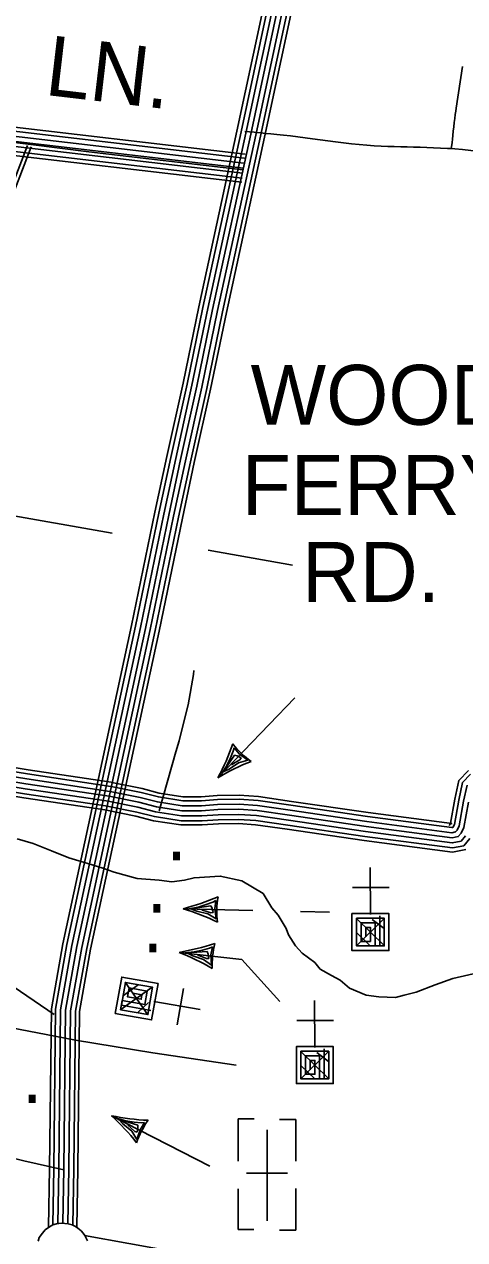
# Model space of a CAD drawing. Extents: x 1788175 to 1969470, y 584502 to 738744.
# Drawn here: x 1837495 to 1840217, y 713422 to 720928 of the extents above; entities that cross this region are included whole.
import ezdxf

# ---------------------------------------------------------------- set-up
doc = ezdxf.new("R2010")
doc.units = 0
for name, color, linetype in [('DESIGN - ROW - Right-of-Way and Easement Labels', 7, 'Continuous'), ('DESIGN - TRANSPORTATION - Text', 7, 'Continuous'), ('DESIGN - UTILITIES - Cable (Overhead) with Text', 7, 'Continuous'), ('DESIGN - UTILITIES - Cable (Underground) with Text', 7, 'Continuous'), ('SURVEY - CENTERLINE - Preliminary Text', 7, 'Continuous'), ('SURVEY - CONTOURS - Index with Text', 7, 'Continuous'), ('SURVEY - TRANSPORTATION - Roads', 7, 'Continuous'), ('SURVEY - VEGETATION - Features with Text', 7, 'Continuous')]:
    doc.layers.add(name, color=color, linetype=linetype)

msp = doc.modelspace()

# ---------------------------------------------------------------- linework, layer by layer
at = {"layer": 'DESIGN - ROW - Right-of-Way and Easement Labels'}
for p, q in [((1837232.7, 717927.5), (1838038.6, 717785.4)), ((1838630.4, 717681), (1839152.6, 717588.9))]:
    msp.add_line(p, q, dxfattribs=at)
at = {"layer": 'DESIGN - TRANSPORTATION - Text'}
msp.add_lwpolyline([(1837451.3, 715898), (1837549.3, 715868.6), (1837662.1, 715824.4), (1837770, 715780.3), (1837887.6, 715746), (1837980.8, 715716.6), (1838049.4, 715692), (1838191.6, 715652.8), (1838328.9, 715643), (1838407.4, 715633.2), (1838485.8, 715643), (1838544.7, 715657.7), (1838706.5, 715667.5), (1838838.8, 715638.1), (1838971.2, 715559.7), (1839025.2, 715471.4), (1839064.4, 715427.3), (1839113.4, 715343.9), (1839128.1, 715304.7), (1839172.2, 715236.1), (1839211.5, 715191.9), (1839289.9, 715133.1), (1839324.2, 715093.9), (1839392.9, 715054.6), (1839446.8, 715025.2), (1839505.7, 714976.2), (1839608.6, 714932.1), (1839687.1, 714922.3), (1839790, 714917.4), (1839844, 714932.1), (1839917.5, 714951.7), (1840035.2, 714995.8), (1840143.1, 715035), (1840314.7, 715074.3)], dxfattribs=at)
at = {"layer": 'DESIGN - UTILITIES - Cable (Overhead) with Text'}
for p, q in [((1838691.7, 716275.5), (1839166.5, 716768.3)), ((1838724.3, 716310.7), (1838795, 716414.6)), ((1838746.8, 716350.8), (1838769.8, 716397.7)), ((1838769.8, 716397.7), (1838786.3, 716439.2)), ((1838786.3, 716439.2), (1838791.1, 716459.5)), ((1838791.1, 716459.5), (1838825.6, 716420.4)), ((1838795, 716414.6), (1838811.5, 716410.5)), ((1838811.5, 716410.5), (1838835.7, 716397.4)), ((1838825.6, 716420.4), (1838877.1, 716383.9)), ((1838835.7, 716397.4), (1838827, 716385.2)), ((1838716.2, 716300.8), (1838746.8, 716350.8)), ((1838760.6, 716328.5), (1838724.3, 716310.7)), ((1838819.1, 716367.9), (1838760.6, 716328.5)), ((1838798, 716369), (1838776.6, 716355.8)), ((1838827, 716385.2), (1838798, 716369)), ((1838877.1, 716383.9), (1838819.1, 716367.9)), ((1838568.6, 715476.8), (1838618.8, 715491.5)), ((1838618.8, 715491.5), (1838660.5, 715507.4)), ((1838660.5, 715507.4), (1838678.8, 715517.6)), ((1838678.8, 715517.6), (1838673.2, 715465.8)), ((1838476, 715466.5), (1838907.6, 715455.9)), ((1838511.2, 715465.5), (1838568.6, 715476.8)), ((1838523.9, 715466.3), (1838648.3, 715484.5)), ((1838561.6, 715451.6), (1838523.9, 715466.3)), ((1838630.1, 715435.1), (1838561.6, 715451.6)), ((1838616.7, 715451.3), (1838592.5, 715458.2)), ((1838648.3, 715441), (1838616.7, 715451.3)), ((1838681.2, 715403.1), (1838630.1, 715435.1)), ((1838648.3, 715484.5), (1838656.4, 715469.5)), ((1838663.1, 715442.8), (1838648.3, 715441)), ((1838656.4, 715469.5), (1838663.1, 715442.8)), ((1838673.2, 715465.8), (1838681.2, 715403.1)), ((1839201.8, 715448.7), (1839382.2, 715444.3)), ((1838486.5, 715193.1), (1838544.7, 715199.8)), ((1838499.2, 715192.8), (1838624.7, 715201.1)), ((1838535.7, 715175.2), (1838499.2, 715192.8)), ((1838544.7, 715199.8), (1838595.8, 715210.5)), ((1838595.8, 715210.5), (1838638.7, 715223)), ((1838624.7, 715201.1), (1838631.6, 715185.5)), ((1838638.7, 715223), (1838657.7, 715231.7)), ((1838657.7, 715231.7), (1838648, 715180.5)), ((1838602.6, 715153.3), (1838535.7, 715175.2)), ((1838590.6, 715170.6), (1838567, 715179.4)), ((1838621.2, 715157.8), (1838590.6, 715170.6)), ((1838651.1, 715117.4), (1838602.6, 715153.3)), ((1838636.2, 715158.3), (1838621.2, 715157.8)), ((1838631.6, 715185.5), (1838636.2, 715158.3)), ((1838648, 715180.5), (1838651.1, 715117.4)), ((1838033.7, 714187.8), (1838642.6, 713875.6)), ((1838065, 714171.7), (1838121.6, 714156.9)), ((1838104.4, 714137.2), (1838076.7, 714166.8)), ((1838076.7, 714166.8), (1838196.7, 714129.1)), ((1838121.6, 714156.9), (1838173.2, 714148.3)), ((1838173.2, 714148.3), (1838217.7, 714144.5)), ((1838238.5, 714145.8), (1838211, 714101.5)), ((1838217.7, 714144.5), (1838238.5, 714145.8)), ((1838158.9, 714092.6), (1838104.4, 714137.2)), ((1838153.9, 714113), (1838135.1, 714129.7)), ((1838177.8, 714090), (1838153.9, 714113)), ((1838191, 714041.6), (1838158.9, 714092.6)), ((1838192, 714085.2), (1838177.8, 714090)), ((1838211, 714101.5), (1838191, 714041.6)), ((1838197.5, 714112.1), (1838192, 714085.2)), ((1838196.7, 714129.1), (1838197.5, 714112.1))]:
    msp.add_line(p, q, dxfattribs=at)
msp.add_lwpolyline([(1838451.5, 715196.8), (1838838.8, 715152.7), (1839074.2, 714892.8)], dxfattribs=at)
for centre, radius, start, end in [((1837323, 717007.6), 1552.3, 331.85818, 340.28596), ((1839205.8, 716809.1), 532.3, 217.64141, 234.49981), ((1839401.4, 715084.5), 1386.4, 111.34988, 120.78842), ((1838090.4, 716970.1), 1552.3, 284.38394, 292.81172), ((1839216.7, 715448.3), 532.3, 170.16717, 187.02557), ((1838078, 714138.5), 1386.4, 63.87564, 73.31418), ((1838186.2, 716726.2), 1552.3, 279.84039, 288.26817), ((1837949.5, 713904.5), 1386.4, 59.33209, 68.77062), ((1839188.4, 715120), 532.3, 165.62362, 182.48201), ((1838339.5, 715709.6), 1552.3, 258.63986, 267.06763), ((1837098.4, 713164.5), 1386.4, 38.13155, 47.57009), ((1838693, 713849.7), 532.3, 144.42308, 161.28148)]:
    msp.add_arc(centre, radius, start, end, dxfattribs=at)
at = {"layer": 'DESIGN - UTILITIES - Cable (Underground) with Text'}
for p, q in [((1839750.6, 715596.6), (1839522.6, 715596.6)), ((1838439.6, 714749.6), (1838479.3, 714974.2)), ((1839406.8, 714775.2), (1839178.7, 714775.2)), ((1838816.2, 714168.4), (1838816.2, 713907.6)), ((1838915.9, 714168.4), (1838816.8, 714168.4)), ((1839172.6, 714164.5), (1839072.8, 714164.5)), ((1839172.5, 713907.7), (1839172.5, 714164.5)), ((1839122.5, 713833.3), (1838868.8, 713833.3)), ((1838816.2, 713736.6), (1838816.2, 713485.2)), ((1839172.5, 713481.2), (1839172.5, 713739.3)), ((1838816.3, 713485.2), (1838914.6, 713485.2)), ((1839172.3, 713481.2), (1839072.8, 713481.2))]:
    msp.add_line(p, q, dxfattribs=at)
for points in [[(1839632.2, 715720.4), (1839634.6, 715430)], [(1839634.5, 715440.9), (1839634.6, 715435.8), (1839748.6, 715435.8), (1839748.6, 715207.7), (1839520.5, 715207.7), (1839520.5, 715435.8), (1839691.6, 715435.8), (1839691.6, 715431.8)], [(1839691.6, 715421.6), (1839691.6, 715236.2), (1839549, 715236.2), (1839549, 715407.3), (1839720.1, 715407.3), (1839720.1, 715236.2), (1839663.1, 715236.2), (1839663.1, 715378.8), (1839577.6, 715378.8), (1839577.6, 715264.8), (1839634.6, 715264.8), (1839634.6, 715350.3), (1839606.1, 715350.3), (1839606.1, 715293.3)], [(1839721.9, 715407.4), (1839546.9, 715235.3)], [(1839549.8, 715404.5), (1839719, 715238.3)], [(1839646.1, 715398.7), (1839719, 715343.2)], [(1839549.8, 715317), (1839631.5, 715238.3)], [(1838306.5, 714891.1), (1838301.5, 714891.9), (1838281.6, 714779.6), (1838057, 714819.3), (1838096.7, 715043.9), (1838321.3, 715004.2), (1838291.5, 714835.8), (1838287.6, 714836.5)], [(1838277.6, 714838.2), (1838095, 714870.5), (1838119.9, 715010.9), (1838288.3, 714981.1), (1838258.5, 714812.6), (1838090.1, 714842.4), (1838100, 714898.6), (1838240.4, 714873.7), (1838255.3, 714958), (1838143, 714977.8), (1838133, 714921.7), (1838217.3, 714906.8), (1838222.2, 714934.9), (1838166.1, 714944.8)], [(1838285.4, 714980.8), (1838092.3, 714843.2)], [(1838199.2, 714996), (1838107.5, 714929.3)], [(1838258.3, 714810.9), (1838119.3, 715013.1)], [(1838582.2, 714844.7), (1838295.7, 714892.9)], [(1839288.3, 714899.1), (1839290.8, 714608.6)], [(1838262.9, 714887.1), (1838195.6, 714824.9)], [(1839290.7, 714619.5), (1839290.8, 714614.5), (1839404.8, 714614.5), (1839404.8, 714386.4), (1839176.7, 714386.4), (1839176.7, 714614.5), (1839347.8, 714614.5), (1839347.8, 714610.4)], [(1839347.8, 714600.2), (1839347.8, 714414.9), (1839205.2, 714414.9), (1839205.2, 714585.9), (1839376.3, 714585.9), (1839376.3, 714414.9), (1839319.3, 714414.9), (1839319.3, 714557.4), (1839233.7, 714557.4), (1839233.7, 714443.4), (1839290.8, 714443.4), (1839290.8, 714528.9), (1839262.2, 714528.9), (1839262.2, 714471.9)], [(1839378.1, 714586), (1839203.1, 714414)], [(1839206, 714583.1), (1839375.2, 714416.9)], [(1839302.2, 714577.3), (1839375.2, 714521.8)], [(1839206, 714495.6), (1839287.7, 714416.9)], [(1838997.1, 714101), (1838997.1, 713538)]]:
    msp.add_lwpolyline(points, dxfattribs=at)
at = {"layer": 'SURVEY - CENTERLINE - Preliminary Text'}
for points in [[(1839972.6, 729378.5), (1840035.9, 728820.7), (1840039.3, 728509.5), (1839986.5, 727386.7), (1839955.2, 726498), (1839902.1, 725627.5), (1839770, 724549.9), (1839681.4, 723978.4), (1839566.7, 723403.2), (1839380, 722558.7), (1839202.9, 721690), (1838895.2, 720250.4), (1838658.8, 719166.3), (1838561.7, 718693), (1838460.9, 718239.8), (1838387.7, 717896.4), (1838243.1, 717197.5), (1837819.5, 715232.8), (1837749.6, 714839.2), (1837739, 713860.1), (1837733.6, 713523.6)], [(1840003.4, 729382), (1840066.9, 728822.6), (1840070.3, 728508.9), (1840017.5, 727385.4), (1839986.1, 726496.5), (1839933, 725624.7), (1839800.7, 724545.7), (1839711.9, 723973), (1839597, 723396.9), (1839410.3, 722552.3), (1839233.2, 721683.7), (1838925.5, 720243.9), (1838689.1, 719159.9), (1838592, 718686.5), (1838491.1, 718233.2), (1838418, 717890), (1838273.5, 717191.1), (1837849.9, 715226.8), (1837780.6, 714836.3), (1837770, 713859.6), (1837764.5, 713520.5)], [(1840034.2, 729385.5), (1840097.9, 728824.6), (1840101.3, 728508.4), (1840048.4, 727384.2), (1840017.1, 726495), (1839963.9, 725621.9), (1839831.4, 724541.4), (1839742.4, 723967.6), (1839627.4, 723390.5), (1839440.6, 722545.8), (1839263.6, 721677.4), (1838955.8, 720237.3), (1838719.5, 719153.5), (1838622.3, 718680), (1838521.4, 718226.6), (1838448.3, 717883.6), (1838303.8, 717184.7), (1837880.4, 715220.8), (1837811.5, 714833.4), (1837800.9, 713859.2), (1837795.4, 713510.9)], [(1840057.7, 729397.4), (1840122.6, 728826.1), (1840126, 728507.9), (1840073.1, 727383.2), (1840041.8, 726493.8), (1839988.5, 725619.6), (1839855.9, 724538), (1839766.8, 723963.3), (1839651.6, 723385.4), (1839464.8, 722540.7), (1839287.7, 721672.3), (1838979.9, 720232.1), (1838743.7, 719148.3), (1838646.5, 718674.9), (1838545.6, 718221.4), (1838472.5, 717878.6), (1838328, 717179.6), (1837904.6, 715216), (1837836.2, 714831.1), (1837825.7, 713858.9), (1837819.9, 713499.2)], [(1839886.4, 729359.3), (1839948.3, 728815.3), (1839951.6, 728511.1), (1839898.8, 727390.3), (1839867.6, 726502.2), (1839814.7, 725635.5), (1839683.1, 724562), (1839595, 723993.7), (1839480.8, 723421.3), (1839294.1, 722577), (1839117, 721708), (1838809.4, 720268.9), (1838573, 719184.4), (1838475.9, 718711.4), (1838375.1, 718258.5), (1838301.8, 717914.4), (1838157.3, 717215.6), (1837733.4, 715249.7), (1837662, 714847.4), (1837651.2, 713861.2), (1837645.4, 713499)], [(1839911.7, 729364.9), (1839974, 728816.9), (1839977.3, 728510.6), (1839924.5, 727389.3), (1839893.2, 726500.9), (1839840.4, 725633.2), (1839708.5, 724558.5), (1839620.3, 723989.2), (1839506, 723416), (1839319.3, 722571.6), (1839142.2, 721702.7), (1838834.6, 720263.5), (1838598.2, 719179.1), (1838501.1, 718706), (1838400.3, 718253), (1838327, 717909.1), (1838182.5, 717210.3), (1837758.7, 715244.7), (1837687.7, 714845), (1837677, 713860.9), (1837671.4, 713512.9)], [(1839941.8, 729375), (1840004.9, 728818.8), (1840008.3, 728510.1), (1839955.5, 727388), (1839924.2, 726499.4), (1839871.3, 725630.4), (1839739.2, 724554.2), (1839650.8, 723983.8), (1839536.3, 723409.6), (1839349.6, 722565.2), (1839172.5, 721696.4), (1838864.9, 720257), (1838628.5, 719172.7), (1838531.4, 718699.5), (1838430.6, 718246.4), (1838357.3, 717902.8), (1838212.8, 717203.9), (1837789.1, 715238.8), (1837718.6, 714842.1), (1837708, 713860.5), (1837702.5, 713521.1)]]:
    msp.add_lwpolyline(points, dxfattribs=at)
at = {"layer": 'SURVEY - CONTOURS - Index with Text'}
msp.add_lwpolyline([(1851668.5, 710218.1), (1850819.3, 710320.4), (1849678.2, 710418.6), (1849294.4, 710465.2), (1849214.5, 710486.9), (1848774.2, 710696.2), (1846649.5, 711685.6), (1845390.2, 712274.5), (1845152.1, 712348.7), (1843927.8, 712625.5), (1842145.7, 712925.5), (1841311.9, 713044.1), (1840980.8, 713061), (1840496.5, 713049.7), (1840098.4, 713053.4), (1839938.2, 713094.5), (1839681.8, 713179.4), (1839542, 713202.9), (1839378.8, 713217.3), (1838414.2, 713348.6), (1837866.1, 713448.2)], dxfattribs=at)
at = {"layer": 'SURVEY - TRANSPORTATION - Roads'}
for points in [[(1838859.4, 720126.6), (1837204.4, 720320.7), (1836659.8, 720388.3), (1836406.6, 720445.7), (1836187.7, 720483.8), (1836015.9, 720500.9), (1835835.6, 720507.6), (1835507.4, 720538), (1834660.2, 720678.2)], [(1838852.8, 720070.3), (1837197.6, 720264.4), (1836650, 720332.4), (1836395.5, 720390.1), (1836180, 720427.6), (1836012.1, 720444.3), (1835832, 720451), (1835500.2, 720481.7), (1834650.9, 720622.3)], [(1838856.4, 720101.1), (1837201.4, 720295.2), (1836655.3, 720363), (1836401.5, 720420.5), (1836184.2, 720458.3), (1836014.2, 720475.2), (1835834, 720481.9), (1835504.1, 720512.5), (1834656, 720652.8)], [(1840133.1, 720160.5), (1840136.7, 720183.1), (1840139, 720198.8), (1840141.4, 720218.9), (1840143.6, 720242), (1840145.9, 720267.5), (1840149.2, 720295.3), (1840152.2, 720322.2), (1840155.5, 720347.6), (1840159.1, 720371.4), (1840162, 720392.8), (1840164.2, 720411.4), (1840203.6, 720668.5)], [(1838842, 719977.9), (1837186.5, 720172.1), (1836633.9, 720240.7), (1836377.2, 720298.9), (1836167.4, 720335.4), (1836005.7, 720351.5), (1835825.9, 720358.1), (1835488.3, 720389.4), (1834635.7, 720530.5)], [(1838845.6, 720008.7), (1837190.2, 720202.9), (1836639.3, 720271.3), (1836383.3, 720329.3), (1836171.6, 720366.1), (1836007.9, 720382.4), (1835827.9, 720389.1), (1835492.2, 720420.2), (1834640.8, 720561.1)], [(1838849.2, 720039.5), (1837193.9, 720233.7), (1836644.6, 720301.8), (1836389.4, 720359.7), (1836175.8, 720396.9), (1836010, 720413.3), (1835829.9, 720420), (1835496.2, 720451), (1834645.8, 720591.7)], [(1838839.1, 719953.4), (1837183.5, 720147.6), (1836629.7, 720216.3), (1836372.3, 720274.6), (1836164.1, 720310.9), (1836004.1, 720326.8), (1835824.3, 720333.4), (1835485.1, 720364.9), (1834631.7, 720506.1)], [(1838858.2, 720267), (1838916, 720261.4), (1838933.6, 720259.6), (1838956.8, 720257.6), (1838985, 720255), (1839017.8, 720251.9), (1839055.2, 720248.4), (1839096.5, 720244.4), (1839140.1, 720239.6), (1839185.3, 720233.8), (1839230.7, 720227.3), (1839276.7, 720221.3), (1839323.4, 720215.1), (1839370.8, 720208.8), (1839419.1, 720202.6), (1839468, 720196.7), (1839516.9, 720190.6), (1839565.4, 720185.5), (1839612.3, 720181.4), (1839657.6, 720178.2), (1839700.5, 720175.6), (1839741.6, 720174), (1839781.9, 720172.7), (1839821.6, 720171.7), (1839861.1, 720170.8), (1839901, 720169.8), (1839941.4, 720168.6), (1839982.6, 720167), (1840024.6, 720165.6), (1840067.3, 720164.1), (1840111.1, 720162), (1840133.1, 720160.5)], [(1837514, 720180.6), (1837237.9, 719465), (1837038.3, 718958.6), (1837024, 718871.7), (1836986.3, 718618), (1836948.3, 718217.5), (1836937.4, 717898.9), (1836938.7, 717844.5)], [(1837537.1, 720171.7), (1837260.9, 719456.1), (1837062.3, 718952), (1837048.4, 718867.8), (1837010.8, 718615), (1836973, 718215.9), (1836962.1, 717898.8), (1836963.4, 717845.1)], [(1838847, 720029.7), (1837894.4, 720141.5), (1837354.9, 720208.4)], [(1840133.1, 720160.5), (1840156.6, 720158.9), (1840204.2, 720154.8), (1840254.3, 720149.9), (1840306.7, 720144.4), (1840360.5, 720138.7), (1840415.1, 720133), (1840468.8, 720126.9), (1840519, 720121), (1840562.8, 720115.5), (1840600.5, 720113.7), (1840630.5, 720119.3)], [(1838451.3, 716503.6), (1838454.4, 716512.9), (1838507.6, 716724.6), (1838540.2, 716911.9), (1838543.3, 716937.5)], [(1838328.2, 716070.4), (1838430.9, 716434.7), (1838451.3, 716503.6), (1838507.6, 716724.6), (1838540.2, 716911.9)], [(1838028.8, 716221.9), (1837514.6, 716299), (1837036.9, 716375.9), (1836513.6, 716478.1)], [(1838032.6, 716247.3), (1837518.6, 716324.4), (1837041.4, 716401.3), (1836518.5, 716503.3)], [(1838019.6, 716160.6), (1837505.1, 716237.7), (1837026, 716314.9), (1836501.7, 716417.2)], [(1838019.6, 716160.6), (1837505.1, 716237.7), (1837026, 716314.9), (1836501.7, 716417.2)], [(1838024.2, 716191.2), (1837509.9, 716268.4), (1837031.4, 716345.4), (1836507.6, 716447.6)], [(1838006.7, 716074.8), (1837491.8, 716152), (1837010.8, 716229.5), (1836485.1, 716332.1)], [(1838010.4, 716099.3), (1837495.6, 716176.5), (1837015.1, 716253.8), (1836489.8, 716356.4)], [(1838015, 716129.9), (1837500.3, 716207.1), (1837020.6, 716284.4), (1836495.8, 716386.8)], [(1838036.8, 716245.6), (1838223.2, 716207.8), (1838328.9, 716180.7), (1838475.7, 716158), (1838588.3, 716158.2), (1838687.9, 716164.7), (1838823.8, 716166.9), (1838942.7, 716158.7), (1839145.6, 716129.3), (1839620.3, 716060.3), (1840136.9, 715992.3), (1840131.2, 715991.2), (1840123, 715981.4), (1840129.5, 715994.7), (1840156.1, 716142.1), (1840181, 716257.2), (1840240.5, 716319.8)], [(1838031.9, 716221.3), (1838217.7, 716183.7), (1838323.9, 716156.5), (1838473.9, 716133.3), (1838589.2, 716133.5), (1838688.9, 716140), (1838823.1, 716142.1), (1838940.1, 716134.1), (1839142.1, 716104.8), (1839616.9, 716035.8), (1840137.7, 715967.2), (1840144.5, 715968.6), (1840143.8, 715967.8), (1840153.2, 715987), (1840180.4, 716137.3), (1840203.7, 716245.2), (1840253.2, 716297.3)], [(1838025.7, 716191), (1838210.7, 716153.5), (1838317.7, 716126.1), (1838471.5, 716102.3), (1838590.2, 716102.5), (1838690.1, 716109), (1838822.3, 716111.1), (1838936.8, 716103.3), (1839137.6, 716074.1), (1839612.6, 716005.1), (1840138.7, 715935.8), (1840161.1, 715940.2), (1840170, 715950.7), (1840182.9, 715977.2), (1840210.8, 716131.3), (1840232.1, 716230.2)], [(1838007.3, 716099.8), (1838189.9, 716062.8), (1838299, 716034.8), (1838464.4, 716009.3), (1838593.3, 716009.5), (1838693.9, 716016.1), (1838819.9, 716018.1), (1838926.9, 716010.8), (1839124.2, 715982.1), (1839599.9, 715913), (1840141.6, 715841.7), (1840211.1, 715855.2), (1840248.5, 715899.5)], [(1838013.4, 716130.2), (1838196.9, 716093), (1838305.2, 716065.2), (1838466.8, 716040.3), (1838592.3, 716040.5), (1838692.7, 716047), (1838820.7, 716049.1), (1838930.2, 716041.6), (1839128.7, 716012.8), (1839604.1, 715943.7), (1840140.6, 715873.1), (1840194.5, 715883.6), (1840222.3, 715916.6)], [(1840241.2, 716125.3), (1840212.7, 715967.5), (1840196.2, 715933.7), (1840177.8, 715911.9), (1840139.7, 715904.5), (1839608.4, 715974.4), (1839133.2, 716043.5), (1838933.5, 716072.5), (1838821.5, 716080.1), (1838691.4, 716078), (1838591.2, 716071.5), (1838469.2, 716071.3), (1838311.4, 716095.6), (1838203.8, 716123.3), (1838019.6, 716160.6)], [(1838019.6, 716160.6), (1838203.8, 716123.3), (1838311.4, 716095.6), (1838469.2, 716071.3), (1838591.2, 716071.5), (1838691.4, 716078), (1838821.5, 716080.1), (1838933.5, 716072.5), (1839133.2, 716043.5), (1839608.4, 715974.4), (1840139.7, 715904.5), (1840177.8, 715911.9), (1840196.2, 715933.7), (1840212.7, 715967.5), (1840241.2, 716125.3)], [(1838002.2, 716074.6), (1838184.2, 716037.7), (1838293.8, 716009.6), (1838462.5, 715983.6), (1838594.2, 715983.8), (1838695, 715990.4), (1838819.2, 715992.3), (1838924.2, 715985.2), (1839120.6, 715956.7), (1839596.4, 715887.5), (1840142.4, 715815.6), (1840224.9, 715831.7)], [(1836885.2, 715800.4), (1836905.8, 715573.6), (1836938.1, 715410.8), (1836973.6, 715334.2), (1837015.9, 715274.8), (1837132, 715186.4), (1837679.4, 714812.4)], [(1838804.4, 714499), (1838290, 714576.2), (1837810.9, 714653.4), (1837286.6, 714755.7)], [(1837738.8, 713852.9), (1837492.7, 713908.6), (1837161.8, 713991.6), (1836631.3, 714109.6), (1836212.3, 714195.9)]]:
    msp.add_lwpolyline(points, dxfattribs=at)
at = {"layer": 'SURVEY - VEGETATION - Features with Text'}
msp.add_lwpolyline([(1837580.5, 713413.6), (1837587.5, 713434.9), (1837606.6, 713462.3), (1837623.2, 713482.9), (1837649.8, 713502.1), (1837671.5, 713513), (1837692.9, 713519.6), (1837708.1, 713521.9), (1837727.1, 713524), (1837746.3, 713522.8), (1837766.7, 713519.9), (1837790.6, 713513.3), (1837810.8, 713503.2), (1837826.2, 713493.9), (1837846.8, 713476.3), (1837859.4, 713461.7), (1837868.2, 713448.2), (1837877.7, 713431.2), (1837884.5, 713415.9)], dxfattribs=at)

# ---------------------------------------------------------------- texts
at = {"layer": 'DESIGN - ROW - Right-of-Way and Easement Labels'}
msp.add_text('LN.', height=370, rotation=353.31008, dxfattribs=at).set_placement((1837614.7, 720493.4))
for s, p in [('WOODS', (1838893.5, 718455)), ('FERRY', (1838839.4, 717898.1)), ('RD.', (1839212.1, 717361.3))]:
    msp.add_text(s, height=370, dxfattribs=at).set_placement(p)
at = {"layer": 'DESIGN - UTILITIES - Cable (Underground) with Text'}
for p in [(1838372.6, 715765.7), (1838250, 715442.1), (1838225.5, 715196.9), (1837480.2, 714265.4)]:
    msp.add_text('.', height=343, dxfattribs=at).set_placement(p)

doc.saveas('drawing.dxf')
